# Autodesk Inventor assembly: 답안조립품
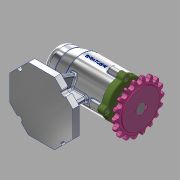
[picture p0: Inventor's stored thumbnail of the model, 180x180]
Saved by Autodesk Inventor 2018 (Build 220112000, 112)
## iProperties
Created: 2021-01
Part Number: 답안조립품
Material: 일반
Document SubType Name: Assembly
Designer: home
Author: home
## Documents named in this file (12)
- C:\Users\home\Desktop\710106V1034\답안조립품.iam
- C:\Users\home\Desktop\710106V1034\본체.ipt
- C:\Users\home\Desktop\710106V1034\커버.ipt
- C:\Users\home\Desktop\710106V1034\축.ipt
- C:\Users\home\Desktop\710106V1034\베어링 6004.ipt
- C:\Users\home\Desktop\710106V1034\어댑터슬리브.ipt
- C:\Users\home\Desktop\710106V1034\베어링 51202.ipt
- C:\Users\home\Desktop\710106V1034\오일 실.ipt
- C:\Users\home\Desktop\710106V1034\Ű 5 x 5 x 14.ipt
- C:\Users\home\Desktop\710106V1034\스프로킷.ipt
- C:\Users\home\Desktop\710106V1034\멈춤나사 M3.ipt
- C:\Users\home\Desktop\710106V1034\볼트 M4.ipt
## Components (1 placed, 1 different names)
1. Ű 5 x 5 x 14:1
